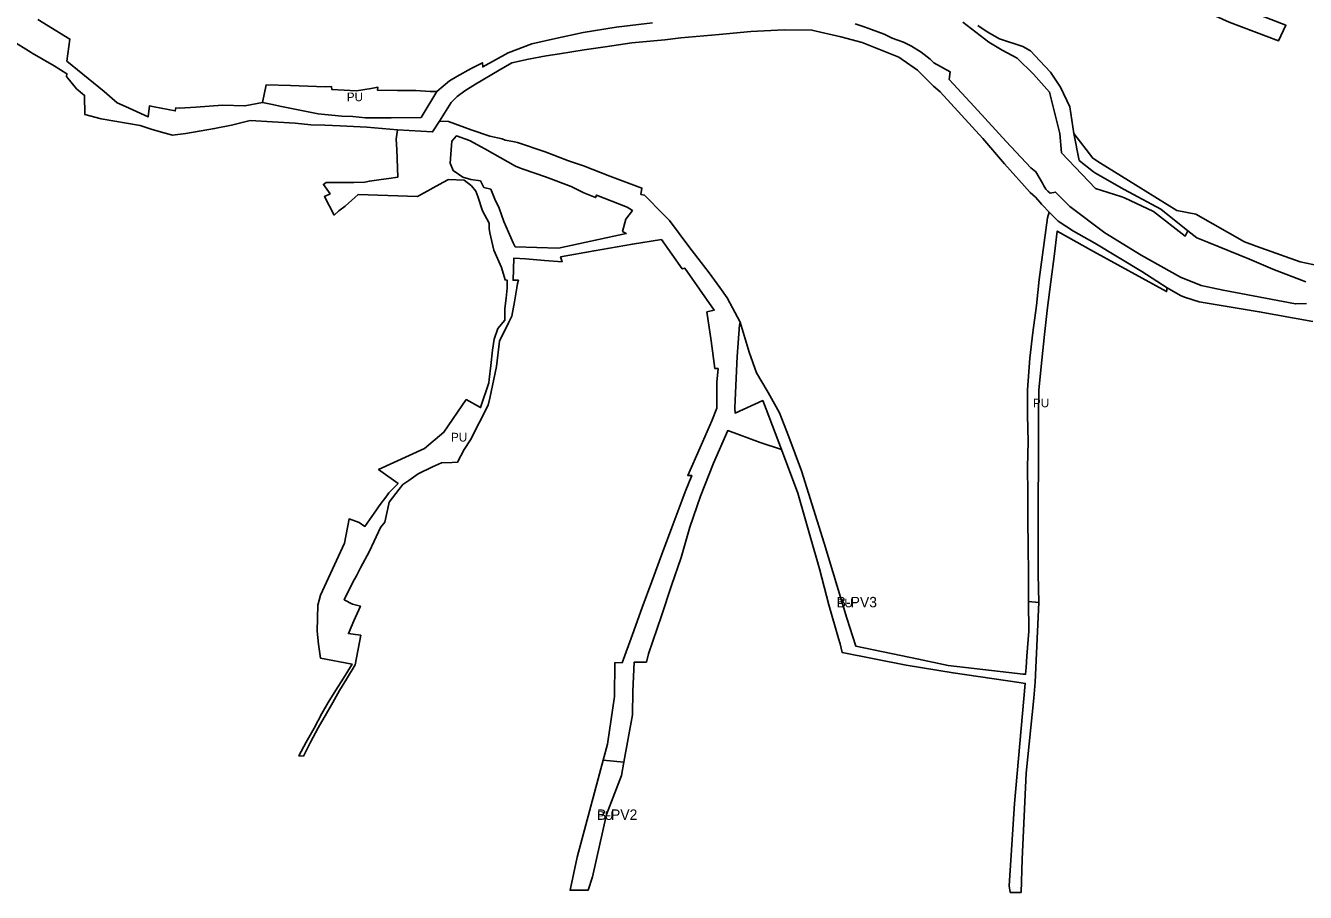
# Model space of a CAD drawing. Extents: x -532083 to -529750, y -1178838 to -1176858.
# Drawn here: x -530875 to -530139, y -1178825 to -1178327 of the extents above; entities that cross this region are included whole.
import ezdxf

# ---------------------------------------------------------------- set-up
doc = ezdxf.new("R2010")
doc.units = 0
for name, color, linetype in [('90320013', 7, 'Continuous'), ('90390023', 7, 'Continuous'), ('90450013', 7, 'Continuous'), ('90450023', 7, 'Continuous'), ('ID_navrh', 7, 'Continuous')]:
    doc.layers.add(name, color=color, linetype=linetype)

msp = doc.modelspace()

# ---------------------------------------------------------------- linework, layer by layer
at = {"layer": '90320013'}
for points in [[(-530867.8193, -1178323.40045), (-530849.3143, -1178334.70345), (-530851.0163, -1178347.33345), (-530829.5983, -1178364.79645), (-530822.2113, -1178371.34445), (-530817.4013, -1178373.41245), (-530804.3453, -1178379.44345), (-530803.5693, -1178373.11345), (-530800.9363, -1178373.62045), (-530788.7913, -1178375.95745), (-530788.4853, -1178374.22245), (-530786.3073, -1178374.44645), (-530776.8593, -1178373.75745), (-530761.5693, -1178372.72345), (-530748.6853, -1178373.06745), (-530738.6253, -1178371.09145), (-530733.7233, -1178372.09745), (-530727.5803, -1178373.35745), (-530706.4933, -1178377.63845), (-530692.9643, -1178378.99345), (-530686.6443, -1178379.22345), (-530679.3443, -1178379.91245), (-530664.5683, -1178379.91145), (-530647.3913, -1178379.79645), (-530638.2563, -1178364.83645), (-530630.9993, -1178358.77345), (-530626.7923, -1178356.15045), (-530618.6083, -1178351.63145), (-530612.1043, -1178348.27645), (-530611.9183, -1178350.69945), (-530597.2553, -1178342.57645), (-530583.6283, -1178337.36945), (-530570.1313, -1178334.36545), (-530554.1763, -1178330.86445), (-530535.2303, -1178327.86345), (-530514.2903, -1178325.36245)], [(-530397.8443, -1178325.89045), (-530392.5753, -1178327.65245), (-530388.3613, -1178329.23745), (-530381.1613, -1178331.87945), (-530376.4203, -1178334.16945), (-530369.9223, -1178336.45945), (-530365.3563, -1178338.74945), (-530359.9123, -1178342.27245), (-530354.6443, -1178346.32345), (-530352.4813, -1178348.32945), (-530343.1843, -1178353.47045), (-530343.6883, -1178357.91645), (-530329.3753, -1178373.52145), (-530310.9573, -1178393.50845), (-530296.7243, -1178408.62345), (-530293.8783, -1178410.97545), (-530290.1033, -1178417.54545), (-530289.2033, -1178419.11145), (-530288.1853, -1178420.88445), (-530286.9693, -1178422.02345), (-530285.6743, -1178423.23545), (-530282.4863, -1178422.68845), (-530274.4203, -1178431.02445), (-530254.1333, -1178445.98045), (-530233.3573, -1178458.97445), (-530210.6253, -1178471.47845), (-530198.8933, -1178476.38245), (-530186.1833, -1178479.07945), (-530144.6313, -1178486.92445), (-530138.2703, -1178486.68845)], [(-530134.6733, -1178497.00145), (-530165.3853, -1178491.40045), (-530199.8863, -1178485.79845), (-530208.4253, -1178483.00245), (-530210.6253, -1178482.02145), (-530218.4473, -1178477.60845), (-530232.9633, -1178468.23545), (-530259.8943, -1178452.06945), (-530272.1933, -1178445.05045), (-530281.0993, -1178439.30745), (-530286.1883, -1178434.20245), (-530287.0493, -1178433.44545), (-530289.1763, -1178431.07545), (-530290.5683, -1178429.52245), (-530291.3343, -1178428.66945), (-530294.0883, -1178425.60045), (-530297.1263, -1178422.95445), (-530311.8603, -1178406.48645), (-530324.2793, -1178391.91745), (-530348.7973, -1178364.95645), (-530352.8163, -1178361.76545), (-530361.8673, -1178352.59745), (-530372.5833, -1178345.03345), (-530378.3393, -1178342.84345), (-530393.8183, -1178336.67245), (-530406.0633, -1178333.48645), (-530422.5933, -1178329.46745), (-530438.6213, -1178329.34145), (-530457.7983, -1178330.32445), (-530475.9183, -1178332.00745), (-530498.0653, -1178334.02745), (-530507.1923, -1178335.04045), (-530526.2863, -1178336.79745), (-530541.5273, -1178339.08145), (-530553.6143, -1178340.83845), (-530567.8033, -1178343.12345), (-530575.5113, -1178344.35345), (-530585.6713, -1178346.28645), (-530595.2143, -1178348.41445), (-530602.4603, -1178352.61645), (-530616.1523, -1178360.69445), (-530622.2833, -1178364.38445), (-530626.5423, -1178367.67345), (-530629.9913, -1178371.06145), (-530636.8223, -1178381.78045), (-530640.7733, -1178388.05045), (-530660.8723, -1178386.80345), (-530669.6783, -1178386.07645), (-530678.4843, -1178385.34845), (-530693.8183, -1178384.51745), (-530702.7273, -1178384.10145), (-530710.8093, -1178383.89345), (-530719.7183, -1178383.06245), (-530732.7723, -1178382.23045), (-530745.6193, -1178381.39945), (-530756.3943, -1178384.10145), (-530766.1333, -1178386.17945), (-530782.7093, -1178388.88145), (-530790.3763, -1178389.92145), (-530796.5923, -1178388.22345), (-530802.6403, -1178386.55045), (-530808.9133, -1178384.42745), (-530831.2653, -1178380.45745), (-530840.8323, -1178378.02945), (-530840.8713, -1178367.09345), (-530845.4483, -1178363.37145), (-530851.3573, -1178356.25345), (-530851.0803, -1178354.58645), (-530858.2803, -1178350.00345), (-530870.9843, -1178342.75045), (-530871.6293, -1178342.35045), (-530883.3793, -1178335.06145)]]:
    msp.add_lwpolyline(points, dxfattribs=at)
at = {"layer": '90390023'}
msp.add_lwpolyline([(-530138.6543, -1178474.28345), (-530157.5403, -1178467.01045), (-530171.0303, -1178461.25945), (-530194.6383, -1178451.61845), (-530201.3833, -1178448.91245), (-530206.4423, -1178444.85245), (-530221.9553, -1178432.50545), (-530243.0333, -1178421.17245), (-530259.4933, -1178411.81445), (-530260.8003, -1178411.07145), (-530268.9313, -1178404.44445), (-530271.9803, -1178388.89645), (-530261.1533, -1178403.19845), (-530256.7713, -1178405.93145), (-530240.5633, -1178416.03645), (-530212.8303, -1178433.32645), (-530201.9133, -1178435.37145), (-530173.9303, -1178451.34045), (-530167.2603, -1178453.72045), (-530141.9503, -1178462.75045), (-530130.9903, -1178465.08045)], dxfattribs=at)
at = {"layer": '90450013'}
msp.add_lwpolyline([(-530327.1373, -1178326.88445), (-530321.9083, -1178330.48145), (-530314.7583, -1178334.52945), (-530301.3483, -1178338.85545), (-530296.8833, -1178341.48745), (-530291.5473, -1178347.09445), (-530285.4483, -1178353.72145), (-530279.6043, -1178362.38845), (-530274.2673, -1178373.60345), (-530271.9803, -1178388.89645), (-530268.9313, -1178404.44445), (-530260.8003, -1178411.07145), (-530259.4933, -1178411.81445), (-530243.0333, -1178421.17245), (-530221.9553, -1178432.50545), (-530206.4423, -1178444.85245), (-530207.9263, -1178447.96045), (-530226.2083, -1178433.85245), (-530242.8593, -1178425.91845), (-530244.9823, -1178425.22645), (-530259.5113, -1178420.49045), (-530279.0763, -1178400.02945), (-530280.1173, -1178388.96345), (-530285.9453, -1178365.16245), (-530295.3113, -1178354.93245), (-530304.6783, -1178345.74545), (-530312.9283, -1178341.27345), (-530313.2503, -1178341.03145), (-530320.8863, -1178336.36645), (-530335.9193, -1178325.05245)], dxfattribs=at)
for points in [[(-530722.4203, -1178361.45845), (-530702.6243, -1178362.20145), (-530698.9373, -1178361.95845), (-530698.6143, -1178363.74445), (-530684.5543, -1178364.36245), (-530676.1403, -1178363.10745), (-530672.3273, -1178362.41445), (-530672.4603, -1178364.01745), (-530660.8703, -1178364.28445), (-530650.4793, -1178364.15145), (-530642.1713, -1178364.83645), (-530638.2563, -1178364.83645), (-530647.3913, -1178379.79645), (-530664.5683, -1178379.91145), (-530679.3443, -1178379.91245), (-530686.6443, -1178379.22345), (-530692.9643, -1178378.99345), (-530706.4933, -1178377.63845), (-530727.5803, -1178373.35745), (-530733.7233, -1178372.09745), (-530738.6253, -1178371.09145), (-530736.4333, -1178360.93245)], [(-530618.6503, -1178386.91345), (-530607.8133, -1178390.55345), (-530600.6643, -1178391.98745), (-530598.9963, -1178392.70445), (-530594.5373, -1178393.60245), (-530592.0323, -1178394.14845), (-530576.0393, -1178399.58845), (-530562.5493, -1178404.61045), (-530553.9533, -1178407.52545), (-530538.8213, -1178413.49745), (-530520.3753, -1178420.33045), (-530520.9513, -1178423.98145), (-530518.9073, -1178424.43745), (-530508.0063, -1178435.59945), (-530504.5993, -1178439.01645), (-530493.4203, -1178453.89545), (-530488.2433, -1178460.57245), (-530481.7713, -1178469.10345), (-530475.6703, -1178477.44945), (-530471.4173, -1178483.38445), (-530463.8283, -1178497.49545), (-530464.3133, -1178498.95745), (-530465.5413, -1178517.18145), (-530466.7153, -1178542.17645), (-530466.9353, -1178546.91945), (-530466.8363, -1178549.67845), (-530450.8753, -1178542.51545), (-530448.9853, -1178547.36145), (-530440.1643, -1178570.53545), (-530452.3453, -1178566.53245), (-530471.0363, -1178559.79045), (-530479.2263, -1178578.54045), (-530486.7863, -1178597.50145), (-530492.8773, -1178615.19845), (-530497.9173, -1178632.68345), (-530503.4643, -1178648.79545), (-530509.2203, -1178666.31045), (-530516.7033, -1178688.05845), (-530517.8543, -1178692.87045), (-530524.7613, -1178692.87045), (-530525.5283, -1178709.61545), (-530525.8393, -1178723.11645), (-530530.7303, -1178750.30845), (-530542.6993, -1178749.15845), (-530540.2403, -1178739.94945), (-530536.1813, -1178712.61545), (-530535.8923, -1178693.13345), (-530531.8113, -1178693.21445), (-530525.7333, -1178676.95545), (-530520.3313, -1178661.37445), (-530514.7033, -1178646.47045), (-530509.0763, -1178631.34045), (-530503.2233, -1178615.53345), (-530497.3703, -1178600.17745), (-530495.5693, -1178594.98345), (-530491.7423, -1178585.49945), (-530493.9933, -1178585.49945), (-530486.9733, -1178569.45145), (-530480.1373, -1178554.18745), (-530477.2703, -1178546.88645), (-530477.2703, -1178531.84445), (-530476.6093, -1178524.10145), (-530478.3733, -1178524.10145), (-530480.5783, -1178508.17345), (-530483.0043, -1178491.58245), (-530478.8143, -1178490.47645), (-530495.8003, -1178466.32245), (-530497.2273, -1178466.84245), (-530509.1483, -1178449.84145), (-530525.8443, -1178452.50345), (-530547.9343, -1178456.40745), (-530567.1243, -1178459.91945), (-530566.3453, -1178462.68845), (-530576.3553, -1178462.01845), (-530587.4333, -1178460.94745), (-530594.1073, -1178460.68045), (-530594.5113, -1178473.28445), (-530591.4383, -1178473.36145), (-530591.8473, -1178475.22045), (-530592.3973, -1178477.71945), (-530593.7063, -1178485.71645), (-530595.1353, -1178493.95745), (-530596.8923, -1178497.37945), (-530602.3473, -1178508.32245), (-530603.9353, -1178522.97945), (-530607.8933, -1178541.20845), (-530608.7613, -1178545.16445), (-530619.0153, -1178565.13245), (-530622.6403, -1178570.60045), (-530626.3973, -1178577.82145), (-530629.4823, -1178578.16745), (-530635.6953, -1178578.39045), (-530640.7983, -1178580.61645), (-530649.1443, -1178584.69045), (-530654.4693, -1178588.46145), (-530657.8543, -1178590.69445), (-530660.0463, -1178593.52045), (-530665.7473, -1178600.92445), (-530666.4783, -1178604.48645), (-530668.1823, -1178612.38345), (-530670.6723, -1178615.50545), (-530674.4073, -1178623.41445), (-530677.3113, -1178629.44945), (-530682.0843, -1178638.19045), (-530684.5733, -1178643.18545), (-530685.8183, -1178645.47445), (-530687.1153, -1178648.04545), (-530691.6063, -1178657.05345), (-530686.7963, -1178659.45145), (-530682.2593, -1178660.67145), (-530686.0343, -1178669.07145), (-530689.1383, -1178676.48445), (-530685.0073, -1178676.95645), (-530682.0783, -1178677.40845), (-530685.3453, -1178694.46945), (-530690.3013, -1178702.60445), (-530694.2433, -1178709.15845), (-530698.0733, -1178716.05045), (-530701.8203, -1178722.37545), (-530706.6293, -1178730.57645), (-530711.0363, -1178738.81945), (-530715.0853, -1178746.94245), (-530717.5863, -1178746.82345), (-530713.5373, -1178738.81945), (-530708.8873, -1178730.85145), (-530704.3813, -1178722.37745), (-530700.8893, -1178716.05045), (-530696.3843, -1178708.93245), (-530691.9913, -1178702.03945), (-530687.0343, -1178694.01745), (-530705.2993, -1178690.54345), (-530706.3603, -1178682.60245), (-530707.1673, -1178675.11045), (-530706.7643, -1178660.12545), (-530705.1493, -1178654.45545), (-530691.4213, -1178624.48545), (-530688.8123, -1178610.55145), (-530682.9823, -1178612.57045), (-530679.7153, -1178614.85345), (-530673.0793, -1178605.35645), (-530671.3983, -1178603.04945), (-530667.0623, -1178597.28045), (-530665.8353, -1178595.46745), (-530660.6173, -1178590.18945), (-530670.4963, -1178583.16545), (-530671.8313, -1178582.21645), (-530645.3563, -1178569.97245), (-530634.2973, -1178560.69445), (-530621.4283, -1178541.93745), (-530613.1843, -1178546.57645), (-530608.3593, -1178532.25645), (-530608.1913, -1178530.32745), (-530607.2973, -1178522.24545), (-530606.3353, -1178513.54645), (-530605.3433, -1178507.24745), (-530603.1953, -1178500.99745), (-530599.1563, -1178496.19245), (-530599.2433, -1178489.63445), (-530598.4533, -1178483.68945), (-530597.9263, -1178477.87645), (-530597.8133, -1178473.28945), (-530599.0343, -1178473.16645), (-530601.1093, -1178466.06245), (-530605.5193, -1178456.02645), (-530607.8743, -1178446.02145), (-530608.1813, -1178443.55045), (-530608.2113, -1178440.48245), (-530612.0523, -1178433.34445), (-530614.7943, -1178425.19745), (-530615.8453, -1178422.20945), (-530618.3773, -1178419.10145), (-530622.6803, -1178415.70545), (-530631.6173, -1178415.35445), (-530634.9073, -1178417.10145), (-530649.4113, -1178425.15345), (-530683.6303, -1178424.02345), (-530691.0933, -1178430.80345), (-530694.6143, -1178433.48745), (-530697.3283, -1178435.88245), (-530702.9493, -1178425.23245), (-530699.7573, -1178423.74445), (-530703.5053, -1178418.22545), (-530701.9963, -1178417.06245), (-530686.0503, -1178417.20545), (-530679.7863, -1178416.91945), (-530677.0833, -1178416.31045), (-530670.2433, -1178415.44245), (-530665.9133, -1178414.92045), (-530660.8363, -1178414.07745), (-530661.3103, -1178398.13945), (-530661.7843, -1178392.19245), (-530660.8723, -1178386.80345), (-530640.7733, -1178388.05045), (-530636.8223, -1178381.78045), (-530631.6173, -1178382.02945)], [(-530623.3263, -1178414.12945), (-530618.7353, -1178415.38445), (-530613.3093, -1178416.17145), (-530611.2523, -1178419.92745), (-530607.2873, -1178420.88745), (-530604.8853, -1178426.67945), (-530602.5673, -1178431.90845), (-530599.8433, -1178439.46445), (-530594.3943, -1178451.84345), (-530593.2723, -1178454.09345), (-530568.4303, -1178454.89745), (-530529.3973, -1178446.45645), (-530531.5283, -1178445.38745), (-530529.5743, -1178438.26045), (-530525.8443, -1178433.27145), (-530528.9043, -1178431.31745), (-530537.6153, -1178427.85845), (-530546.4733, -1178424.34045), (-530547.0573, -1178425.80945), (-530553.8603, -1178423.10845), (-530561.0133, -1178419.37445), (-530575.7563, -1178413.85145), (-530588.7223, -1178409.39745), (-530590.7513, -1178408.66545), (-530593.1623, -1178407.79445), (-530610.7703, -1178397.81545), (-530619.6303, -1178392.96845), (-530627.0213, -1178390.34345), (-530629.6393, -1178393.43245), (-530630.2553, -1178400.84645), (-530630.7173, -1178405.94245), (-530629.0233, -1178410.26745)], [(-530272.1933, -1178445.05045), (-530259.8943, -1178452.06945), (-530232.9633, -1178468.23545), (-530218.4473, -1178477.60845), (-530218.6913, -1178479.81445), (-530260.7423, -1178456.74945), (-530281.5233, -1178445.05045), (-530283.2193, -1178458.23845), (-530285.3403, -1178474.19045), (-530287.2483, -1178489.08045), (-530288.9453, -1178504.60745), (-530290.4293, -1178519.28445), (-530292.1763, -1178536.37745), (-530292.3163, -1178551.33945), (-530292.4303, -1178566.41245), (-530292.4303, -1178581.59845), (-530292.5443, -1178597.01345), (-530292.5443, -1178626.58845), (-530292.4933, -1178642.26545), (-530292.2243, -1178658.50245), (-530298.0243, -1178658.09645), (-530298.1583, -1178642.26545), (-530298.3003, -1178626.16845), (-530298.4143, -1178611.44345), (-530298.4143, -1178596.03345), (-530298.7553, -1178580.85045), (-530298.3003, -1178566.12545), (-530298.7553, -1178550.82945), (-530298.6413, -1178536.33245), (-530297.3893, -1178518.18245), (-530295.6823, -1178503.45745), (-530293.5203, -1178487.93245), (-530291.9133, -1178472.91445), (-530287.2483, -1178437.39345), (-530286.1883, -1178434.20245), (-530281.0993, -1178439.30745)]]:
    msp.add_lwpolyline(points, close=True, dxfattribs=at)
at = {"layer": '90450023'}
for points in [[(-530214.6993, -1178252.18345), (-530213.7103, -1178271.52945), (-530212.4393, -1178280.16945), (-530208.3353, -1178288.40145), (-530188.2193, -1178311.53945), (-530178.8193, -1178315.64945), (-530150.1113, -1178326.73345), (-530154.4243, -1178335.78745), (-530182.6253, -1178324.89945), (-530194.2883, -1178319.80045), (-530216.7173, -1178294.00245), (-530222.1003, -1178283.20345), (-530223.6733, -1178272.51545), (-530224.7153, -1178252.13345), (-530221.8493, -1178205.35845), (-530227.1863, -1178138.60145), (-530228.1323, -1178116.05145), (-530242.0943, -1178087.56745), (-530224.8663, -1178080.68945), (-530218.2293, -1178113.53445), (-530217.2033, -1178137.99345), (-530211.8243, -1178205.26545)], [(-530303.4863, -1178704.61545), (-530341.5003, -1178699.06845), (-530368.5043, -1178694.52145), (-530405.3293, -1178687.32245), (-530406.4623, -1178682.39745), (-530407.4063, -1178679.36645), (-530412.8823, -1178659.85445), (-530418.3593, -1178639.20545), (-530423.7843, -1178619.83245), (-530430.7143, -1178595.81645), (-530440.1643, -1178570.53545), (-530448.9853, -1178547.36145), (-530450.8753, -1178542.51545), (-530466.8363, -1178549.67845), (-530466.9353, -1178546.91945), (-530466.7153, -1178542.17645), (-530465.5413, -1178517.18145), (-530464.3133, -1178498.95745), (-530463.8283, -1178497.49545), (-530458.8073, -1178514.71645), (-530454.5963, -1178526.57545), (-530448.3363, -1178536.89245), (-530447.7953, -1178537.78545), (-530441.3173, -1178549.48245), (-530435.9723, -1178563.29245), (-530428.5733, -1178582.87245), (-530415.5303, -1178624.41745), (-530402.4883, -1178667.57045), (-530397.4543, -1178683.63745), (-530361.3283, -1178691.11145), (-530344.3333, -1178694.71145), (-530304.4873, -1178699.44645), (-530301.3973, -1178699.69445), (-530299.7663, -1178699.82545), (-530299.5173, -1178695.94145), (-530299.1033, -1178689.48745), (-530297.8893, -1178675.14445), (-530298.0243, -1178658.09645), (-530292.2243, -1178658.50245), (-530294.2473, -1178704.37145), (-530295.0563, -1178713.57145), (-530299.3893, -1178756.64145), (-530301.7933, -1178806.21445), (-530302.3453, -1178825.24745), (-530308.5643, -1178825.21545), (-530309.2763, -1178821.52745), (-530307.7443, -1178797.81445), (-530306.2123, -1178774.10145), (-530303.0843, -1178739.61645), (-530299.9553, -1178705.13045)], [(-530561.4833, -1178823.02345), (-530557.6323, -1178805.08445), (-530542.6993, -1178749.15845), (-530530.7303, -1178750.30845), (-530532.1063, -1178757.95845), (-530540.7243, -1178780.48645), (-530548.8193, -1178816.37645), (-530551.3503, -1178823.99445), (-530561.6903, -1178823.98545)]]:
    msp.add_lwpolyline(points, close=True, dxfattribs=at)

# ---------------------------------------------------------------- texts
at = {"layer": '90450013'}
for rotation, p in [(0.00000003, (-530690.07411, -1178370.42245)), (0.00000004, (-530295.49487, -1178546.35245)), (0.00000003, (-530630.1471, -1178566.04445))]:
    msp.add_text('PU', height=5, rotation=rotation, dxfattribs=at).set_placement(p)
at = {"layer": '90450023'}
for p in [(-530408.40918, -1178661.37145), (-530546.2103, -1178783.55839)]:
    msp.add_text('PU', height=5, rotation=359.99999998, dxfattribs=at).set_placement(p)
at = {"layer": 'ID_navrh'}
msp.add_text('B-PV3', height=6, rotation=359.99999999, dxfattribs=at).set_placement((-530408.40918, -1178661.37145))
msp.add_text('B-PV2', height=6, dxfattribs=at).set_placement((-530546.2103, -1178783.55839))

doc.saveas('drawing.dxf')
